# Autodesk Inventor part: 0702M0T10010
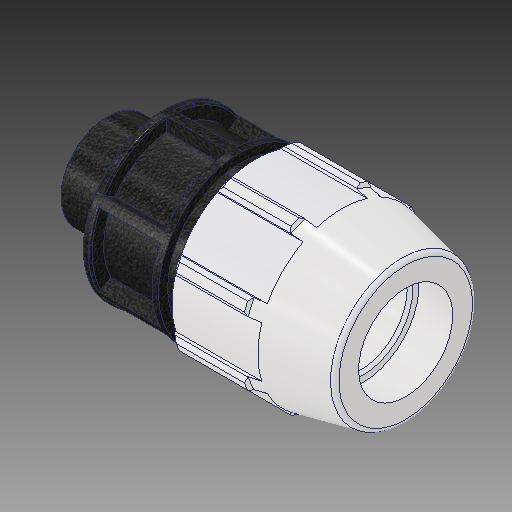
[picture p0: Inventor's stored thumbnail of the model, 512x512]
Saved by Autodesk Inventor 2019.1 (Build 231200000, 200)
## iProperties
Created: 2017-02
Part Number: 0702M0T10010
Material: PVC-Piping
Description: PLASSON MALE ADAPTOR 1'' - 1''M
Document SubType Name: Modeling
Designer: KIM
Mass: 92.6774 g
Surface Area: 199.44 cm^2
Volume: 66.1981 cm^3
Density: 1.4 g/cm^3
Appearance: PTFE
Author: KIM
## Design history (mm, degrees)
derived "0702M0T.ipt"
feature "Solid1::0702M0T.ipt"
tag "TaggingFeature1"
body "Solid1"
other parameters: "d2" = 33.3, "d4" = 15.13114, "d5" = 26.4795, "d7" = 64.008, "d8" = 48.006, "d9" = 15.13114, "d11" = 3.02623, "d12" = 51.2064, "d13" = 120 deg, "d14" = 49.95, "d15" = 12 deg, "d16" = 57.6072, "d18" = 1.665, "d19" = 35 deg, "d20" = 17.5 deg, "d21" = 59.52744, "d23" = 0, "d25" = 360 deg, "d27" = 1.28016, "d34" = 3.2004, "d36" = 0, "d42" = 26.4795, "d43" = 1.92024, "d46" = 0.999, "d51" = 105.918, "d52" = 20.066, "d53" = 0.666, "d55" = 360 deg, "d57" = 33.249, "d58" = 23.2743, "d59" = 21.1836, "d61" = 25.146, "d_" = 33.3, "E_" = 64.008, "H_" = 105.918, "l_" = 82.042, "l_2" = 20.066, "G_" = 33.249
